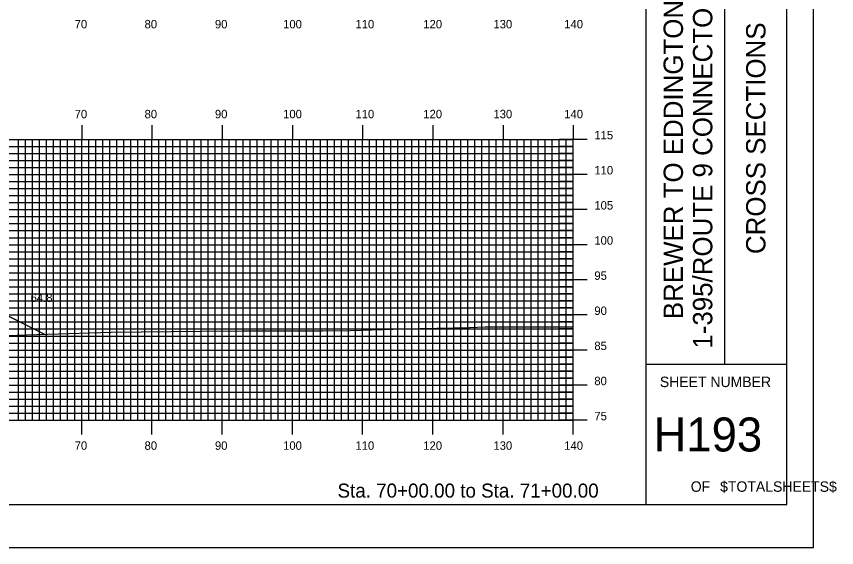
# Model space of a CAD drawing. Extents: x 1760217 to 1760560, y 442591 to 442811.
# Drawn here: x 1760443.4 to 1760560.2, y 442590.5 to 442666.2 of the extents above; entities that cross this region are included whole.
import ezdxf

# ---------------------------------------------------------------- set-up
doc = ezdxf.new("R2010")
doc.units = 0
for name, color, linetype in [('BORDER', 7, 'Continuous'), ('D_Roadway_Centerline', 7, 'Continuous'), ('D_Roadway_SlopeLines', 7, 'Continuous'), ('D_Text_Standard', 7, 'Continuous'), ('H_V ANNOTATION', 7, 'Continuous'), ('MAJOR', 7, 'Continuous'), ('MINOR', 7, 'Continuous'), ('PLOT BOUNDARY', 7, 'Continuous'), ('S_Roadway_Centerline', 7, 'Continuous')]:
    doc.layers.add(name, color=color, linetype=linetype)

msp = doc.modelspace()

# ---------------------------------------------------------------- linework, layer by layer
at = {"layer": 'BORDER'}
for p, q in [((1760533.1, 442596.67), (1760533.1, 442806.67)), ((1760544.28, 442616.67), (1760544.28, 442686.67)), ((1760533.1, 442616.67), (1760553.1, 442616.67))]:
    msp.add_line(p, q, dxfattribs=at)
msp.add_lwpolyline([(1760233.1, 442596.67), (1760553.1, 442596.67), (1760553.1, 442806.67), (1760233.1, 442806.67)], close=True, dxfattribs=at)
at = {"layer": 'D_Roadway_Centerline'}
msp.add_lwpolyline([(1760431.04, 442629.14), (1760447.52, 442620.9)], dxfattribs=at)
at = {"layer": 'D_Roadway_SlopeLines'}
msp.add_lwpolyline([(1760410.19, 442639.57), (1760447.52, 442620.9)], dxfattribs=at)
at = {"layer": 'MAJOR'}
for p, q in [((1760452.7, 442650.67), (1760452.7, 442648.67)), ((1760462.7, 442650.67), (1760462.7, 442648.67)), ((1760472.7, 442650.67), (1760472.7, 442648.67)), ((1760482.7, 442650.67), (1760482.7, 442648.67)), ((1760492.7, 442650.67), (1760492.7, 442648.67)), ((1760502.7, 442650.67), (1760502.7, 442648.67)), ((1760512.7, 442650.67), (1760512.7, 442648.67)), ((1760522.7, 442650.67), (1760522.7, 442648.67)), ((1760242.7, 442648.67), (1760522.7, 442648.67)), ((1760242.7, 442648.67), (1760522.7, 442648.67)), ((1760452.7, 442608.67), (1760452.7, 442648.67)), ((1760462.7, 442608.67), (1760462.7, 442648.67)), ((1760472.7, 442608.67), (1760472.7, 442648.67)), ((1760482.7, 442608.67), (1760482.7, 442648.67)), ((1760492.7, 442608.67), (1760492.7, 442648.67)), ((1760502.7, 442608.67), (1760502.7, 442648.67)), ((1760512.7, 442608.67), (1760512.7, 442648.67)), ((1760524.7, 442648.67), (1760520.7, 442648.67)), ((1760522.7, 442608.67), (1760522.7, 442648.67)), ((1760522.7, 442608.67), (1760522.7, 442648.67)), ((1760242.7, 442643.67), (1760522.7, 442643.67)), ((1760524.7, 442643.67), (1760520.7, 442643.67)), ((1760242.7, 442638.67), (1760522.7, 442638.67)), ((1760524.7, 442638.67), (1760520.7, 442638.67)), ((1760242.7, 442633.67), (1760522.7, 442633.67)), ((1760524.7, 442633.67), (1760520.7, 442633.67)), ((1760242.7, 442628.67), (1760522.7, 442628.67)), ((1760524.7, 442628.67), (1760520.7, 442628.67)), ((1760242.7, 442623.67), (1760522.7, 442623.67)), ((1760524.7, 442623.67), (1760520.7, 442623.67)), ((1760242.7, 442618.67), (1760522.7, 442618.67)), ((1760524.7, 442618.67), (1760520.7, 442618.67)), ((1760242.7, 442613.67), (1760522.7, 442613.67)), ((1760524.7, 442613.67), (1760520.7, 442613.67)), ((1760242.7, 442608.67), (1760522.7, 442608.67)), ((1760242.7, 442608.67), (1760522.7, 442608.67)), ((1760452.7, 442606.66), (1760452.7, 442608.67)), ((1760462.7, 442606.66), (1760462.7, 442608.67)), ((1760472.7, 442606.66), (1760472.7, 442608.67)), ((1760482.7, 442606.66), (1760482.7, 442608.67)), ((1760492.7, 442606.66), (1760492.7, 442608.67)), ((1760502.7, 442606.66), (1760502.7, 442608.67)), ((1760512.7, 442606.66), (1760512.7, 442608.67)), ((1760524.7, 442608.67), (1760520.7, 442608.67)), ((1760522.7, 442606.66), (1760522.7, 442608.67))]:
    msp.add_line(p, q, dxfattribs=at)
at = {"layer": 'MINOR'}
for p, q in [((1760443.7, 442608.67), (1760443.7, 442648.67)), ((1760444.7, 442608.67), (1760444.7, 442648.67)), ((1760445.7, 442608.67), (1760445.7, 442648.67)), ((1760446.7, 442608.67), (1760446.7, 442648.67)), ((1760447.7, 442608.67), (1760447.7, 442648.67)), ((1760448.7, 442608.67), (1760448.7, 442648.67)), ((1760449.7, 442608.67), (1760449.7, 442648.67)), ((1760450.7, 442608.67), (1760450.7, 442648.67)), ((1760451.7, 442608.67), (1760451.7, 442648.67)), ((1760453.7, 442608.67), (1760453.7, 442648.67)), ((1760454.7, 442608.67), (1760454.7, 442648.67)), ((1760455.7, 442608.67), (1760455.7, 442648.67)), ((1760456.7, 442608.67), (1760456.7, 442648.67)), ((1760457.7, 442608.67), (1760457.7, 442648.67)), ((1760458.7, 442608.67), (1760458.7, 442648.67)), ((1760459.7, 442608.67), (1760459.7, 442648.67)), ((1760460.7, 442608.67), (1760460.7, 442648.67)), ((1760461.7, 442608.67), (1760461.7, 442648.67)), ((1760463.7, 442608.67), (1760463.7, 442648.67)), ((1760464.7, 442608.67), (1760464.7, 442648.67)), ((1760465.7, 442608.67), (1760465.7, 442648.67)), ((1760466.7, 442608.67), (1760466.7, 442648.67)), ((1760467.7, 442608.67), (1760467.7, 442648.67)), ((1760468.7, 442608.67), (1760468.7, 442648.67)), ((1760469.7, 442608.67), (1760469.7, 442648.67)), ((1760470.7, 442608.67), (1760470.7, 442648.67)), ((1760471.7, 442608.67), (1760471.7, 442648.67)), ((1760473.7, 442608.67), (1760473.7, 442648.67)), ((1760474.7, 442608.67), (1760474.7, 442648.67)), ((1760475.7, 442608.67), (1760475.7, 442648.67)), ((1760476.7, 442608.67), (1760476.7, 442648.67)), ((1760477.7, 442608.67), (1760477.7, 442648.67)), ((1760478.7, 442608.67), (1760478.7, 442648.67)), ((1760479.7, 442608.67), (1760479.7, 442648.67)), ((1760480.7, 442608.67), (1760480.7, 442648.67)), ((1760481.7, 442608.67), (1760481.7, 442648.67)), ((1760483.7, 442608.67), (1760483.7, 442648.67)), ((1760484.7, 442608.67), (1760484.7, 442648.67)), ((1760485.7, 442608.67), (1760485.7, 442648.67)), ((1760486.7, 442608.67), (1760486.7, 442648.67)), ((1760487.7, 442608.67), (1760487.7, 442648.67)), ((1760488.7, 442608.67), (1760488.7, 442648.67)), ((1760489.7, 442608.67), (1760489.7, 442648.67)), ((1760490.7, 442608.67), (1760490.7, 442648.67)), ((1760491.7, 442608.67), (1760491.7, 442648.67)), ((1760493.7, 442608.67), (1760493.7, 442648.67)), ((1760494.7, 442608.67), (1760494.7, 442648.67)), ((1760495.7, 442608.67), (1760495.7, 442648.67)), ((1760496.7, 442608.67), (1760496.7, 442648.67)), ((1760497.7, 442608.67), (1760497.7, 442648.67)), ((1760498.7, 442608.67), (1760498.7, 442648.67)), ((1760499.7, 442608.67), (1760499.7, 442648.67)), ((1760500.7, 442608.67), (1760500.7, 442648.67)), ((1760501.7, 442608.67), (1760501.7, 442648.67)), ((1760503.7, 442608.67), (1760503.7, 442648.67)), ((1760504.7, 442608.67), (1760504.7, 442648.67)), ((1760505.7, 442608.67), (1760505.7, 442648.67)), ((1760506.7, 442608.67), (1760506.7, 442648.67)), ((1760507.7, 442608.67), (1760507.7, 442648.67)), ((1760508.7, 442608.67), (1760508.7, 442648.67)), ((1760509.7, 442608.67), (1760509.7, 442648.67)), ((1760510.7, 442608.67), (1760510.7, 442648.67)), ((1760511.7, 442608.67), (1760511.7, 442648.67)), ((1760513.7, 442608.67), (1760513.7, 442648.67)), ((1760514.7, 442608.67), (1760514.7, 442648.67)), ((1760515.7, 442608.67), (1760515.7, 442648.67)), ((1760516.7, 442608.67), (1760516.7, 442648.67)), ((1760517.7, 442608.67), (1760517.7, 442648.67)), ((1760518.7, 442608.67), (1760518.7, 442648.67)), ((1760519.7, 442608.67), (1760519.7, 442648.67)), ((1760520.7, 442608.67), (1760520.7, 442648.67)), ((1760521.7, 442608.67), (1760521.7, 442648.67)), ((1760242.7, 442647.67), (1760522.7, 442647.67)), ((1760522.7, 442647.67), (1760520.7, 442647.67)), ((1760242.7, 442646.67), (1760522.7, 442646.67)), ((1760522.7, 442646.67), (1760520.7, 442646.67)), ((1760242.7, 442645.67), (1760522.7, 442645.67)), ((1760242.7, 442644.67), (1760522.7, 442644.67)), ((1760522.7, 442645.67), (1760520.7, 442645.67)), ((1760522.7, 442644.67), (1760520.7, 442644.67)), ((1760242.7, 442642.67), (1760522.7, 442642.67)), ((1760522.7, 442642.67), (1760520.7, 442642.67)), ((1760242.7, 442641.67), (1760522.7, 442641.67)), ((1760522.7, 442641.67), (1760520.7, 442641.67)), ((1760242.7, 442640.67), (1760522.7, 442640.67)), ((1760522.7, 442640.67), (1760520.7, 442640.67)), ((1760242.7, 442639.67), (1760522.7, 442639.67)), ((1760522.7, 442639.67), (1760520.7, 442639.67)), ((1760242.7, 442637.67), (1760522.7, 442637.67)), ((1760522.7, 442637.67), (1760520.7, 442637.67)), ((1760242.7, 442636.67), (1760522.7, 442636.67)), ((1760522.7, 442636.67), (1760520.7, 442636.67)), ((1760242.7, 442635.67), (1760522.7, 442635.67)), ((1760522.7, 442635.67), (1760520.7, 442635.67)), ((1760242.7, 442634.67), (1760522.7, 442634.67)), ((1760522.7, 442634.67), (1760520.7, 442634.67)), ((1760242.7, 442632.67), (1760522.7, 442632.67)), ((1760522.7, 442632.67), (1760520.7, 442632.67)), ((1760242.7, 442631.67), (1760522.7, 442631.67)), ((1760242.7, 442630.67), (1760522.7, 442630.67)), ((1760522.7, 442631.67), (1760520.7, 442631.67)), ((1760522.7, 442630.67), (1760520.7, 442630.67)), ((1760242.7, 442629.67), (1760522.7, 442629.67)), ((1760522.7, 442629.67), (1760520.7, 442629.67)), ((1760242.7, 442627.67), (1760522.7, 442627.67)), ((1760522.7, 442627.67), (1760520.7, 442627.67)), ((1760242.7, 442626.67), (1760522.7, 442626.67)), ((1760522.7, 442626.67), (1760520.7, 442626.67)), ((1760242.7, 442625.67), (1760522.7, 442625.67)), ((1760522.7, 442625.67), (1760520.7, 442625.67)), ((1760242.7, 442624.67), (1760522.7, 442624.67)), ((1760522.7, 442624.67), (1760520.7, 442624.67)), ((1760242.7, 442622.67), (1760522.7, 442622.67)), ((1760522.7, 442622.67), (1760520.7, 442622.67)), ((1760242.7, 442621.67), (1760522.7, 442621.67)), ((1760522.7, 442621.67), (1760520.7, 442621.67)), ((1760242.7, 442620.67), (1760522.7, 442620.67)), ((1760522.7, 442620.67), (1760520.7, 442620.67)), ((1760242.7, 442619.67), (1760522.7, 442619.67)), ((1760522.7, 442619.67), (1760520.7, 442619.67)), ((1760242.7, 442617.67), (1760522.7, 442617.67)), ((1760242.7, 442616.67), (1760522.7, 442616.67)), ((1760522.7, 442617.67), (1760520.7, 442617.67)), ((1760522.7, 442616.67), (1760520.7, 442616.67)), ((1760242.7, 442615.67), (1760522.7, 442615.67)), ((1760522.7, 442615.67), (1760520.7, 442615.67)), ((1760242.7, 442614.67), (1760522.7, 442614.67)), ((1760522.7, 442614.67), (1760520.7, 442614.67)), ((1760242.7, 442612.67), (1760522.7, 442612.67)), ((1760522.7, 442612.67), (1760520.7, 442612.67)), ((1760242.7, 442611.67), (1760522.7, 442611.67)), ((1760522.7, 442611.67), (1760520.7, 442611.67)), ((1760242.7, 442610.67), (1760522.7, 442610.67)), ((1760242.7, 442609.67), (1760522.7, 442609.67)), ((1760522.7, 442610.67), (1760520.7, 442610.67)), ((1760522.7, 442609.67), (1760520.7, 442609.67))]:
    msp.add_line(p, q, dxfattribs=at)
at = {"layer": 'PLOT BOUNDARY'}
msp.add_lwpolyline([(1760216.91, 442590.55), (1760556.91, 442590.55), (1760556.91, 442810.55), (1760216.91, 442810.55)], close=True, dxfattribs=at)
at = {"layer": 'S_Roadway_Centerline'}
msp.add_lwpolyline([(1760440.45, 442620.7), (1760447.81, 442620.91), (1760456.9, 442621.21), (1760469.72, 442621.36), (1760475.54, 442621.43), (1760482.45, 442621.42), (1760487.05, 442621.41), (1760490.98, 442621.46), (1760498.55, 442621.68), (1760507.9, 442621.9), (1760510.16, 442621.96), (1760512.16, 442621.98), (1760522.36, 442621.97), (1760522.7, 442621.97)], dxfattribs=at)

# ---------------------------------------------------------------- texts
at = {"layer": 'BORDER'}
for s, p in [('1-395/ROUTE 9 CONNECTOR', (1760542.5, 442618.87)), ('BREWER TO EDDINGTON', (1760538.32, 442623.07)), ('CROSS SECTIONS', (1760550.07, 442632.34))]:
    msp.add_text(s, height=2.7557, rotation=90, dxfattribs=at).set_placement(p)
for s, height, p in [('SHEET NUMBER', 1.4905, (1760535.03, 442613.4)), ('H193', 4.839, (1760534.13, 442604.23)), ('OF', 1.491, (1760539.43, 442598.49)), ('$TOTALSHEETS$', 1.4905, (1760543.61, 442598.49))]:
    msp.add_text(s, height=height, dxfattribs=at).set_placement(p)
at = {"layer": 'D_Text_Standard'}
msp.add_text("64.8'", height=1.2, dxfattribs=at).set_placement((1760445.42, 442625.52))
at = {"layer": 'H_V ANNOTATION'}
for s, height, p in [('70', 1.2, (1760451.7, 442664.47)), ('80', 1.2, (1760461.65, 442664.47)), ('90', 1.2, (1760471.67, 442664.47)), ('100', 1.2, (1760481.38, 442664.47)), ('110', 1.2, (1760491.68, 442664.47)), ('120', 1.2, (1760501.34, 442664.47)), ('130', 1.2, (1760511.33, 442664.47)), ('140', 1.2, (1760521.41, 442664.47)), ('70', 1.2, (1760451.7, 442651.67)), ('80', 1.2, (1760461.65, 442651.67)), ('90', 1.2, (1760471.67, 442651.67)), ('100', 1.2, (1760481.38, 442651.67)), ('110', 1.2, (1760491.68, 442651.67)), ('120', 1.2, (1760501.34, 442651.67)), ('130', 1.2, (1760511.33, 442651.67)), ('140', 1.2, (1760521.41, 442651.67)), ('115', 1.2, (1760525.7, 442648.67)), ('110', 1.2, (1760525.7, 442643.67)), ('105', 1.2, (1760525.7, 442638.67)), ('100', 1.2, (1760525.7, 442633.67)), ('95', 1.2, (1760525.7, 442628.67)), ('90', 1.2, (1760525.7, 442623.67)), ('85', 1.2, (1760525.7, 442618.67)), ('80', 1.2, (1760525.7, 442613.67)), ('75', 1.2, (1760525.7, 442608.67)), ('70', 1.2, (1760451.7, 442604.47)), ('80', 1.2, (1760461.65, 442604.47)), ('90', 1.2, (1760471.67, 442604.47)), ('100', 1.2, (1760481.38, 442604.47)), ('110', 1.2, (1760491.68, 442604.47)), ('120', 1.2, (1760501.34, 442604.47)), ('130', 1.2, (1760511.33, 442604.47)), ('140', 1.2, (1760521.41, 442604.47)), ('Sta. 70+00.00 to Sta. 71+00.00', 2.0004, (1760489.13, 442597.66))]:
    msp.add_text(s, height=height, dxfattribs=at).set_placement(p)

doc.saveas('drawing.dxf')
